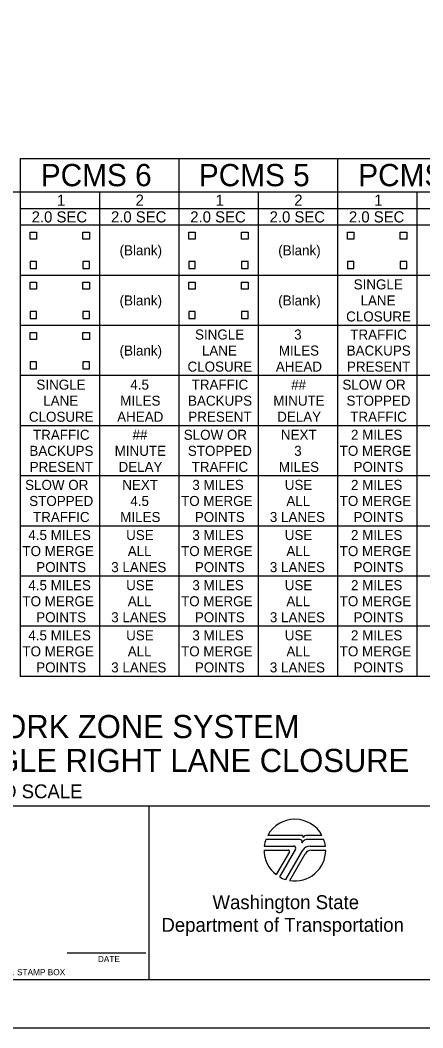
# Model space of a CAD drawing. Extents: x 99999.1 to 100055.7, y 99995 to 100017.5.
# Drawn here: x 100009.47 to 100012.09, y 99999.69 to 100006.22 of the extents above; entities that cross this region are included whole.
import ezdxf

# ---------------------------------------------------------------- set-up
doc = ezdxf.new("R2010")
doc.units = 0
for name, color, linetype in [('SH_DE_DetailHeading1Text', 7, 'Continuous'), ('SH_DE_DetailHeading3Text', 7, 'Continuous'), ('SH_GI_PlotLimits', 7, 'Continuous'), ('SH_GI_SheetBorder', 7, 'Continuous'), ('SH_GI_SheetTextInCells', 7, 'Continuous'), ('SH_GI_WSDOTLogo', 7, 'Continuous'), ('TR_WZ_WorkZoneDetails', 7, 'Continuous'), ('TR_WZ_WorkZoneTextCurrent', 7, 'Continuous')]:
    doc.layers.add(name, color=color, linetype=linetype)

msp = doc.modelspace()

# ---------------------------------------------------------------- linework, layer by layer
at = {"layer": 'SH_GI_PlotLimits'}
msp.add_lwpolyline([(99999.0625, 99999.6875), (100016.0625, 99999.6875), (100016.0625, 100010.6875), (99999.0625, 100010.6875)], close=True, dxfattribs=at)
at = {"layer": 'SH_GI_SheetBorder'}
for p, q in [((100000, 100001.1259), (100015.75, 100001.1259)), ((100010.3089, 100001.1259), (100010.3089, 100000)), ((100009.7797, 100000.1733), (100010.2914, 100000.1733)), ((100000, 100000), (100015.75, 100000))]:
    msp.add_line(p, q, dxfattribs=at)
at = {"layer": 'SH_GI_WSDOTLogo'}
for p, q in [((100011.2894, 100000.9094), (100011.0697, 100000.9094)), ((100011.303, 100000.9354), (100011.0815, 100000.9354)), ((100011.433, 100000.9354), (100011.3351, 100000.9354)), ((100011.343, 100000.9094), (100011.3429, 100000.9094)), ((100011.4448, 100000.9094), (100011.343, 100000.9094)), ((100011.0572, 100000.84), (100011.2148, 100000.84)), ((100011.059, 100000.8661), (100011.2496, 100000.8661)), ((100011.222, 100000.8277), (100011.1364, 100000.6807)), ((100011.261, 100000.8464), (100011.1567, 100000.6672)), ((100011.1989, 100000.6487), (100011.3089, 100000.839)), ((100011.2244, 100000.6428), (100011.3242, 100000.8156)), ((100011.3558, 100000.8661), (100011.4555, 100000.8661)), ((100011.3655, 100000.8394), (100011.4572, 100000.8394))]:
    msp.add_line(p, q, dxfattribs=at)
for centre, radius, start, end in [((100011.2572, 100000.84), 0.2, 28.47865, 151.53204), ((100011.2572, 100000.84), 0.2, 159.69598, 172.50569), ((100011.2894, 100000.8946), 0.0148, 327.8418, 89.99855), ((100011.3429, 100000.861), 0.0484, 89.99529, 147.82376), ((100011.303, 100000.9263), 0.00903, 329.87418, 90.00328), ((100011.3352, 100000.9066), 0.0287, 90.00721, 148.16763), ((100011.2572, 100000.84), 0.2, 7.49431, 20.29406), ((100011.2572, 100000.84), 0.2, 179.99864, 232.84327), ((100011.2149, 100000.8318), 0.0082, 329.74356, 90), ((100011.2572, 100000.84), 0.2, 260.54554, 359.80857), ((100011.2497, 100000.853), 0.0131, 329.76834, 90), ((100011.3558, 100000.8119), 0.0542, 90, 149.99738), ((100011.3654, 100000.7918), 0.0476, 90, 150.05432), ((100011.2572, 100000.84), 0.2, 239.79292, 253.0448)]:
    msp.add_arc(centre, radius, start, end, dxfattribs=at)
at = {"layer": 'TR_WZ_WorkZoneDetails'}
for p, q in [((100009.475, 100005.3241), (100009.475, 100004.9991)), ((100009.475, 100005.3241), (100010.5042, 100005.3241)), ((100010.5042, 100005.3241), (100011.5333, 100005.3241)), ((100010.5042, 100005.3241), (100010.5042, 100004.9991)), ((100011.5333, 100005.3241), (100012.5625, 100005.3241)), ((100011.5333, 100005.3241), (100011.5333, 100004.9991)), ((100011.5333, 100005.3241), (100011.5333, 100004.9991)), ((100009.475, 100005.1075), (100009.475, 100004.9991)), ((100009.9896, 100005.1075), (100009.9896, 100004.9991)), ((100011.0187, 100005.1075), (100011.0187, 100004.9991)), ((100012.0479, 100005.1075), (100012.0479, 100004.9991)), ((100009.475, 100004.9991), (100009.475, 100004.8908)), ((100009.9896, 100004.9991), (100009.9896, 100004.8908)), ((100010.5042, 100004.9991), (100010.5042, 100004.8908)), ((100011.0187, 100004.9991), (100011.0187, 100004.8908)), ((100011.5333, 100004.9991), (100011.5333, 100004.8908)), ((100011.5333, 100004.9991), (100011.5333, 100004.8908)), ((100012.0479, 100004.9991), (100012.0479, 100004.8908)), ((100009.475, 100004.8908), (100009.475, 100004.5658)), ((100010.5042, 100004.8908), (100009.475, 100004.8908)), ((100009.9896, 100004.8908), (100009.9896, 100004.5658)), ((100010.5042, 100004.8908), (100010.5042, 100004.5658)), ((100011.5333, 100004.8908), (100010.5042, 100004.8908)), ((100011.0187, 100004.8908), (100011.0187, 100004.5658)), ((100011.5333, 100004.8908), (100011.5333, 100004.5658)), ((100011.5333, 100004.8908), (100011.5333, 100004.5658)), ((100012.5625, 100004.8908), (100011.5333, 100004.8908)), ((100012.0479, 100004.8908), (100012.0479, 100004.5658)), ((100009.475, 100004.5658), (100009.475, 100004.2408)), ((100010.5042, 100004.5658), (100009.475, 100004.5658)), ((100009.9896, 100004.5658), (100009.9896, 100004.2408)), ((100010.5042, 100004.5658), (100010.5042, 100004.2408)), ((100011.5333, 100004.5658), (100010.5042, 100004.5658)), ((100011.0187, 100004.5658), (100011.0187, 100004.2408)), ((100011.5333, 100004.5658), (100011.5333, 100004.2408)), ((100012.5625, 100004.5658), (100011.5333, 100004.5658)), ((100011.5333, 100004.5658), (100011.5333, 100004.2408)), ((100012.0479, 100004.5658), (100012.0479, 100004.2408)), ((100009.475, 100004.2408), (100009.475, 100003.9158)), ((100010.5042, 100004.2408), (100009.475, 100004.2408)), ((100010.5042, 100004.2408), (100009.475, 100004.2408)), ((100009.9896, 100004.2408), (100009.9896, 100003.9158)), ((100010.5042, 100004.2408), (100010.5042, 100003.9158)), ((100011.5333, 100004.2408), (100010.5042, 100004.2408)), ((100011.5333, 100004.2408), (100010.5042, 100004.2408)), ((100011.0187, 100004.2408), (100011.0187, 100003.9158)), ((100011.5333, 100004.2408), (100011.5333, 100003.9158)), ((100012.5625, 100004.2408), (100011.5333, 100004.2408)), ((100012.5625, 100004.2408), (100011.5333, 100004.2408)), ((100011.5333, 100004.2408), (100011.5333, 100003.9158)), ((100012.0479, 100004.2408), (100012.0479, 100003.9158)), ((100009.475, 100003.9158), (100009.475, 100003.5908)), ((100010.5042, 100003.9158), (100009.475, 100003.9158)), ((100009.9896, 100003.9158), (100009.9896, 100003.5908)), ((100010.5042, 100003.9158), (100010.5042, 100003.5908)), ((100011.5333, 100003.9158), (100010.5042, 100003.9158)), ((100011.0187, 100003.9158), (100011.0187, 100003.5908)), ((100011.5333, 100003.9158), (100011.5333, 100003.5908)), ((100012.5625, 100003.9158), (100011.5333, 100003.9158)), ((100011.5333, 100003.9158), (100011.5333, 100003.5908)), ((100012.0479, 100003.9158), (100012.0479, 100003.5908)), ((100009.475, 100003.5908), (100009.475, 100003.2658)), ((100010.5042, 100003.5908), (100009.475, 100003.5908)), ((100009.9896, 100003.5908), (100009.9896, 100003.2658)), ((100010.5042, 100003.5908), (100010.5042, 100003.2658)), ((100011.5333, 100003.5908), (100010.5042, 100003.5908)), ((100011.0187, 100003.5908), (100011.0187, 100003.2658)), ((100011.5333, 100003.5908), (100011.5333, 100003.2658)), ((100012.5625, 100003.5908), (100011.5333, 100003.5908)), ((100011.5333, 100003.5908), (100011.5333, 100003.2658)), ((100012.0479, 100003.5908), (100012.0479, 100003.2658)), ((100009.475, 100003.2658), (100009.475, 100002.9408)), ((100010.5042, 100003.2658), (100009.475, 100003.2658)), ((100009.9896, 100003.2658), (100009.9896, 100002.9408)), ((100010.5042, 100003.2658), (100010.5042, 100002.9408)), ((100011.5333, 100003.2658), (100010.5042, 100003.2658)), ((100011.0187, 100003.2658), (100011.0187, 100002.9408)), ((100011.5333, 100003.2658), (100011.5333, 100002.9408)), ((100012.5625, 100003.2658), (100011.5333, 100003.2658)), ((100011.5333, 100003.2658), (100011.5333, 100002.9408)), ((100012.0479, 100003.2658), (100012.0479, 100002.9408)), ((100009.475, 100002.9408), (100009.475, 100002.6158)), ((100010.5042, 100002.9408), (100009.475, 100002.9408)), ((100009.9896, 100002.9408), (100009.9896, 100002.6158)), ((100011.5333, 100002.9408), (100010.5042, 100002.9408)), ((100010.5042, 100002.9408), (100010.5042, 100002.6158)), ((100011.0187, 100002.9408), (100011.0187, 100002.6158)), ((100012.5625, 100002.9408), (100011.5333, 100002.9408)), ((100011.5333, 100002.9408), (100011.5333, 100002.6158)), ((100011.5333, 100002.9408), (100011.5333, 100002.6158)), ((100012.0479, 100002.9408), (100012.0479, 100002.6158)), ((100010.5042, 100002.6158), (100009.475, 100002.6158)), ((100009.475, 100002.6158), (100009.475, 100002.2908)), ((100010.5042, 100002.6158), (100009.475, 100002.6158)), ((100009.9896, 100002.6158), (100009.9896, 100002.2908)), ((100011.5333, 100002.6158), (100010.5042, 100002.6158)), ((100011.5333, 100002.6158), (100010.5042, 100002.6158)), ((100010.5042, 100002.6158), (100010.5042, 100002.2908)), ((100011.0187, 100002.6158), (100011.0187, 100002.2908)), ((100012.5625, 100002.6158), (100011.5333, 100002.6158)), ((100012.5625, 100002.6158), (100011.5333, 100002.6158)), ((100011.5333, 100002.6158), (100011.5333, 100002.2908)), ((100011.5333, 100002.6158), (100011.5333, 100002.2908)), ((100012.0479, 100002.6158), (100012.0479, 100002.2908)), ((100009.475, 100002.2908), (100009.475, 100001.9658)), ((100010.5042, 100002.2908), (100009.475, 100002.2908)), ((100009.9896, 100002.2908), (100009.9896, 100001.9658)), ((100010.5042, 100002.2908), (100010.5042, 100001.9658)), ((100011.5333, 100002.2908), (100010.5042, 100002.2908)), ((100011.0187, 100002.2908), (100011.0187, 100001.9658)), ((100011.5333, 100002.2908), (100011.5333, 100001.9658)), ((100011.5333, 100002.2908), (100011.5333, 100001.9658)), ((100012.5625, 100002.2908), (100011.5333, 100002.2908)), ((100012.0479, 100002.2908), (100012.0479, 100001.9658)), ((100010.5042, 100001.9658), (100009.475, 100001.9658)), ((100011.5333, 100001.9658), (100010.5042, 100001.9658)), ((100012.5625, 100001.9658), (100011.5333, 100001.9658))]:
    msp.add_line(p, q, dxfattribs=at)
for points in [[(100008.4458, 100005.1075), (100009.475, 100005.1075)], [(100009.475, 100005.1075), (100010.5042, 100005.1075)], [(100010.5042, 100005.1075), (100011.5333, 100005.1075)], [(100011.5333, 100005.1075), (100012.5625, 100005.1075)], [(100009.475, 100004.9991), (100010.5042, 100004.9991)], [(100010.5042, 100004.9991), (100011.5333, 100004.9991)], [(100011.5333, 100004.9991), (100012.5625, 100004.9991)]]:
    msp.add_lwpolyline(points, dxfattribs=at)
at = {"layer": 'TR_WZ_WorkZoneTextCurrent'}
for points in [[(100009.5393, 100004.8456), (100009.5822, 100004.8456), (100009.5822, 100004.8005), (100009.5393, 100004.8005)], [(100009.8824, 100004.8456), (100009.9253, 100004.8456), (100009.9253, 100004.8005), (100009.8824, 100004.8005)], [(100010.5685, 100004.8456), (100010.6114, 100004.8456), (100010.6114, 100004.8005), (100010.5685, 100004.8005)], [(100010.9115, 100004.8456), (100010.9544, 100004.8456), (100010.9544, 100004.8005), (100010.9115, 100004.8005)], [(100011.5977, 100004.8456), (100011.6405, 100004.8456), (100011.6405, 100004.8005), (100011.5977, 100004.8005)], [(100011.9407, 100004.8456), (100011.9836, 100004.8456), (100011.9836, 100004.8005), (100011.9407, 100004.8005)], [(100009.5393, 100004.6109), (100009.5822, 100004.6109), (100009.5822, 100004.6561), (100009.5393, 100004.6561)], [(100009.8824, 100004.6109), (100009.9253, 100004.6109), (100009.9253, 100004.6561), (100009.8824, 100004.6561)], [(100010.5685, 100004.6109), (100010.6114, 100004.6109), (100010.6114, 100004.6561), (100010.5685, 100004.6561)], [(100010.9115, 100004.6109), (100010.9544, 100004.6109), (100010.9544, 100004.6561), (100010.9115, 100004.6561)], [(100011.5977, 100004.6109), (100011.6405, 100004.6109), (100011.6405, 100004.6561), (100011.5977, 100004.6561)], [(100011.9407, 100004.6109), (100011.9836, 100004.6109), (100011.9836, 100004.6561), (100011.9407, 100004.6561)], [(100009.5393, 100004.5206), (100009.5822, 100004.5206), (100009.5822, 100004.4755), (100009.5393, 100004.4755)], [(100009.8824, 100004.5206), (100009.9253, 100004.5206), (100009.9253, 100004.4755), (100009.8824, 100004.4755)], [(100010.5685, 100004.5206), (100010.6114, 100004.5206), (100010.6114, 100004.4755), (100010.5685, 100004.4755)], [(100010.9115, 100004.5206), (100010.9544, 100004.5206), (100010.9544, 100004.4755), (100010.9115, 100004.4755)], [(100009.5393, 100004.2859), (100009.5822, 100004.2859), (100009.5822, 100004.3311), (100009.5393, 100004.3311)], [(100009.8824, 100004.2859), (100009.9253, 100004.2859), (100009.9253, 100004.3311), (100009.8824, 100004.3311)], [(100010.5685, 100004.2859), (100010.6114, 100004.2859), (100010.6114, 100004.3311), (100010.5685, 100004.3311)], [(100010.9115, 100004.2859), (100010.9544, 100004.2859), (100010.9544, 100004.3311), (100010.9115, 100004.3311)], [(100009.5393, 100004.1956), (100009.5822, 100004.1956), (100009.5822, 100004.1505), (100009.5393, 100004.1505)], [(100009.8824, 100004.1956), (100009.9253, 100004.1956), (100009.9253, 100004.1505), (100009.8824, 100004.1505)], [(100009.5393, 100003.9609), (100009.5822, 100003.9609), (100009.5822, 100004.0061), (100009.5393, 100004.0061)], [(100009.8824, 100003.9609), (100009.9253, 100003.9609), (100009.9253, 100004.0061), (100009.8824, 100004.0061)]]:
    msp.add_lwpolyline(points, close=True, dxfattribs=at)

# ---------------------------------------------------------------- texts
at = {"layer": 'SH_DE_DetailHeading1Text'}
for s, p in [('9-MILE SMART WORK ZONE SYSTEM', (100007.7097, 100001.5658)), ('FREEWAY (3 LANES): SINGLE RIGHT LANE CLOSURE', (100006.8609, 100001.3458))]:
    msp.add_text(s, height=0.15, dxfattribs=at).set_placement(p)
at = {"layer": 'SH_DE_DetailHeading3Text'}
msp.add_text('NOT TO SCALE', height=0.09, dxfattribs=at).set_placement((100008.9969, 100001.1759))
at = {"layer": 'SH_GI_SheetTextInCells'}
for s, height, p in [('Washington State', 0.090072, (100010.7229, 100000.4571)), ('Department of Transportation', 0.090072, (100010.3916, 100000.3101)), ('DATE', 0.04003, (100009.9794, 100000.1141)), ('P.E. STAMP BOX', 0.040032, (100009.339, 100000.0286))]:
    msp.add_text(s, height=height, dxfattribs=at).set_placement(p)
at = {"layer": 'TR_WZ_WorkZoneTextCurrent'}
for s, height, p in [('PCMS 6', 0.14444, (100009.6091, 100005.1436)), ('PCMS 5', 0.14444, (100010.6345, 100005.1436)), ('PCMS 4', 0.14444, (100011.6687, 100005.1436)), ('1', 0.0722, (100009.7142, 100005.0172)), ('2', 0.0722, (100010.2242, 100005.0172)), ('1', 0.0722, (100010.7433, 100005.0172)), ('2', 0.0722, (100011.2534, 100005.0172)), ('1', 0.0722, (100011.7725, 100005.0172)), ('2.0 SEC', 0.07222, (100009.5497, 100004.9088)), ('2.0 SEC', 0.07222, (100010.0643, 100004.9088)), ('2.0 SEC', 0.07222, (100010.5788, 100004.9088)), ('2.0 SEC', 0.07222, (100011.0934, 100004.9088)), ('2.0 SEC', 0.07222, (100011.608, 100004.9088)), ('(Blank)', 0.065, (100010.1202, 100004.6958)), ('(Blank)', 0.065, (100011.1494, 100004.6958)), ('SINGLE', 0.065, (100011.6389, 100004.4748)), ('(Blank)', 0.065, (100010.1202, 100004.3708)), ('(Blank)', 0.065, (100011.1494, 100004.3708)), ('LANE', 0.065, (100011.6832, 100004.3708)), ('CLOSURE', 0.065, (100011.59, 100004.2668)), ('SINGLE', 0.065, (100010.6097, 100004.1498)), ('3', 0.065, (100011.253, 100004.1498)), ('TRAFFIC', 0.065, (100011.6168, 100004.1498)), ('(Blank)', 0.065, (100010.1202, 100004.0458)), ('LANE', 0.065, (100010.654, 100004.0458)), ('MILES', 0.065, (100011.1534, 100004.0458)), ('BACKUPS', 0.065, (100011.5935, 100004.0458)), ('CLOSURE', 0.065, (100010.5608, 100003.9418)), ('AHEAD', 0.065, (100011.1337, 100003.9418)), ('PRESENT', 0.065, (100011.5952, 100003.9418)), ('SINGLE', 0.065, (100009.5806, 100003.8248)), ('4.5', 0.065, (100010.1899, 100003.8248)), ('TRAFFIC', 0.065, (100010.5877, 100003.8248)), ('##', 0.065, (100011.2332, 100003.8248)), ('SLOW OR', 0.065, (100011.5657, 100003.8248)), ('LANE', 0.065, (100009.6248, 100003.7208)), ('MILES', 0.065, (100010.1243, 100003.7208)), ('BACKUPS', 0.065, (100010.5643, 100003.7208)), ('MINUTE', 0.065, (100011.1174, 100003.7208)), ('STOPPED', 0.065, (100011.5923, 100003.7208)), ('CLOSURE', 0.065, (100009.5317, 100003.6168)), ('AHEAD', 0.065, (100010.1045, 100003.6168)), ('PRESENT', 0.065, (100010.566, 100003.6168)), ('DELAY', 0.065, (100011.1424, 100003.6168)), ('TRAFFIC', 0.065, (100011.6168, 100003.6168)), ('TRAFFIC', 0.065, (100009.5585, 100003.4998)), ('##', 0.065, (100010.2041, 100003.4998)), ('SLOW OR', 0.065, (100010.5365, 100003.4998)), ('NEXT', 0.065, (100011.1668, 100003.4998)), ('2 MILES', 0.065, (100011.6214, 100003.4998)), ('BACKUPS', 0.065, (100009.5351, 100003.3958)), ('MINUTE', 0.065, (100010.0882, 100003.3958)), ('STOPPED', 0.065, (100010.5631, 100003.3958)), ('3', 0.065, (100011.253, 100003.3958)), ('TO MERGE', 0.065, (100011.5481, 100003.3958)), ('PRESENT', 0.065, (100009.5369, 100003.2918)), ('DELAY', 0.065, (100010.1132, 100003.2918)), ('TRAFFIC', 0.065, (100010.5877, 100003.2918)), ('MILES', 0.065, (100011.1534, 100003.2918)), ('POINTS', 0.065, (100011.6378, 100003.2918)), ('SLOW OR', 0.065, (100009.5073, 100003.1748)), ('NEXT', 0.065, (100010.1377, 100003.1748)), ('3 MILES', 0.065, (100010.5922, 100003.1748)), ('USE', 0.065, (100011.1919, 100003.1748)), ('2 MILES', 0.065, (100011.6214, 100003.1748)), ('STOPPED', 0.065, (100009.534, 100003.0708)), ('4.5', 0.065, (100010.1899, 100003.0708)), ('TO MERGE', 0.065, (100010.5189, 100003.0708)), ('ALL', 0.065, (100011.2024, 100003.0708)), ('TO MERGE', 0.065, (100011.5481, 100003.0708)), ('TRAFFIC', 0.065, (100009.5585, 100002.9668)), ('MILES', 0.065, (100010.1243, 100002.9668)), ('POINTS', 0.065, (100010.6086, 100002.9668)), ('3 LANES', 0.065, (100011.0951, 100002.9668)), ('POINTS', 0.065, (100011.6378, 100002.9668)), ('4.5 MILES', 0.065, (100009.5281, 100002.8498)), ('USE', 0.065, (100010.1627, 100002.8498)), ('3 MILES', 0.065, (100010.5922, 100002.8498)), ('USE', 0.065, (100011.1919, 100002.8498)), ('2 MILES', 0.065, (100011.6214, 100002.8498)), ('TO MERGE', 0.065, (100009.4897, 100002.7458)), ('ALL', 0.065, (100010.1732, 100002.7458)), ('TO MERGE', 0.065, (100010.5189, 100002.7458)), ('ALL', 0.065, (100011.2024, 100002.7458)), ('TO MERGE', 0.065, (100011.5481, 100002.7458)), ('POINTS', 0.065, (100009.5794, 100002.6418)), ('3 LANES', 0.065, (100010.066, 100002.6418)), ('POINTS', 0.065, (100010.6086, 100002.6418)), ('3 LANES', 0.065, (100011.0951, 100002.6418)), ('POINTS', 0.065, (100011.6378, 100002.6418)), ('4.5 MILES', 0.065, (100009.5281, 100002.5248)), ('USE', 0.065, (100010.1627, 100002.5248)), ('3 MILES', 0.065, (100010.5922, 100002.5248)), ('USE', 0.065, (100011.1919, 100002.5248)), ('2 MILES', 0.065, (100011.6214, 100002.5248)), ('TO MERGE', 0.065, (100009.4897, 100002.4208)), ('ALL', 0.065, (100010.1732, 100002.4208)), ('TO MERGE', 0.065, (100010.5189, 100002.4208)), ('ALL', 0.065, (100011.2024, 100002.4208)), ('TO MERGE', 0.065, (100011.5481, 100002.4208)), ('POINTS', 0.065, (100009.5794, 100002.3168)), ('3 LANES', 0.065, (100010.066, 100002.3168)), ('POINTS', 0.065, (100010.6086, 100002.3168)), ('3 LANES', 0.065, (100011.0951, 100002.3168)), ('POINTS', 0.065, (100011.6378, 100002.3168)), ('4.5 MILES', 0.065, (100009.5281, 100002.1998)), ('USE', 0.065, (100010.1627, 100002.1998)), ('3 MILES', 0.065, (100010.5922, 100002.1998)), ('USE', 0.065, (100011.1919, 100002.1998)), ('2 MILES', 0.065, (100011.6214, 100002.1998)), ('TO MERGE', 0.065, (100009.4897, 100002.0958)), ('ALL', 0.065, (100010.1732, 100002.0958)), ('TO MERGE', 0.065, (100010.5189, 100002.0958)), ('ALL', 0.065, (100011.2024, 100002.0958)), ('TO MERGE', 0.065, (100011.5481, 100002.0958)), ('POINTS', 0.065, (100009.5794, 100001.9918)), ('3 LANES', 0.065, (100010.066, 100001.9918)), ('POINTS', 0.065, (100010.6086, 100001.9918)), ('3 LANES', 0.065, (100011.0951, 100001.9918)), ('POINTS', 0.065, (100011.6378, 100001.9918))]:
    msp.add_text(s, height=height, rotation=360, dxfattribs=at).set_placement(p)

doc.saveas('drawing.dxf')
